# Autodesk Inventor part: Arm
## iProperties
Created: 2006-11
Part Number: Arm
Document SubType Name: Modeling
Designer: nfjf
Author: nfjf
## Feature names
1. Extrusion1
2. Fillet1
3. Extrusion2
4. Extrusion3
5. Fillet2
6. Extrusion4
7. Extrusion5
8. Extrusion6
9. Fillet3
